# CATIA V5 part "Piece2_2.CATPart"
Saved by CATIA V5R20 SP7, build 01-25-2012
Part number: Pièce2
Bounding box of the stored display mesh (mm): x 0 to 5, y -23.352 to 40.116, z -50.015 to 35.141
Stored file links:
  F:\Piece2_2.CATPart
  C:\Users\ASUS\Desktop\Think Motion IAO\Skl_general.CATPart
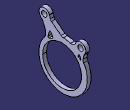
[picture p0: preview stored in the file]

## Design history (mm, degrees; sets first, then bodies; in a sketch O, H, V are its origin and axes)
Body1 (main body)
  Plane1: stored without definition
  Point1 "Point.O": stored without definition
  Point2 "Point.D": stored without definition
  Point3 "Point.D": stored without definition
  Point4 "Point.B": stored without definition
  Point5 "Point.B": stored without definition
  Point6 "Point.D": stored without definition
  Point7 "Point.O": stored without definition
  Sketch1 on Plane1, origin (0, 0, 0), H (0, 1, 0), V (0, 0, 1)
    point P1 (2.9564, 12.9973)
    point P2 (-9.6276, 30.0906)
    point P3 (-22.686, 25.1744)
    arc A1 centre (-16.3583, 28.1678) radius 7 from (-9.6276, 30.0906) to (-21.7119, 23.6578) ccw
    line L1 (22.0467, 10.3647) -> (25.3667, 16.3534)
    point P5 (22.0467, 10.3647)
    line L2 (34.2527, 0.0973) -> (36.2782, 8.4386)
    point P7 (34.2527, 0.0973)
    arc A2 centre (31.305, 13.0613) radius 6.7898 from (36.2782, 8.4386) to (25.3667, 16.3534) ccw
    point P10 (25.3667, 16.3534)
    reference projected point E1 (31.305, 13.0613) from Point5
    reference projected point E2 (-16.3583, 28.1678) from Point6
    arc A3 centre (8.3692, -18.2843) radius 31.7465 from (34.2527, 0.0973) to (-14.5587, 3.6736) cw
    point P12 (34.2527, 0.0973)
    arc A4 centre (8.3692, -18.2843) radius 31.7465 from (22.0467, 10.3647) to (7.0921, 13.4365) ccw
    circle A5 centre (7.024, -18.726) radius 25.5
    reference projected point E3 (7.024, -18.726) from Point7
    arc A6 centre (15.8049, 35.6351) radius 26.0299 from (-9.6276, 30.0906) to (-7.9884, 25.0788) ccw
    axis line L3 (-16.3583, 28.1678) -> (8.3692, -18.2843)
    point P16 (-14.5587, 3.6736)
    point P17 (-21.7119, 23.6578)
    arc A7 centre (-40.513, 5.6558) radius 26.0299 from (-21.7119, 23.6578) to (-14.5587, 3.6736) cw
    line L4 (-7.9884, 25.0788) -> (7.0921, 13.4365)
    point P20 (7.0921, 13.4365)
    point P21 (29.9184, 6.4146)
    line L5 (29.9184, 6.4146) -> (27.7656, 2.2888)
    line L6 (27.7656, 2.2888) -> (31.9929, -0.9748)
    line L7 (31.9929, -0.9748) -> (29.9184, 6.4146)
    point P24 (29.9184, 6.4146)
    point P25 (-8.5711, 13.539)
    line L8 (-8.5711, 13.539) -> (-4.577, 6.0359)
    line L9 (-4.577, 6.0359) -> (-11.9787, 3.0784)
    line L10 (-11.9787, 3.0784) -> (-8.9445, 14.2404)
    point P28 (-8.9445, 14.2404)
    line L11 (-8.9445, 14.2404) -> (-8.5711, 13.539)
    radius A5 = 25.5
    length L8 = 8.5
    coincidence: A1 P3, A2 P10, P10 L1, P12 L2, A3 P1, P7 P12, A6 P5, P20 A3, P21 A2, P24 L5, P24 A2, P25 L3, P28 L3
    tangency: L1 A2, L4 A5, L5 A6, L9 A2
    concentricity: A2 E1, A1 E2, A4 A3, A5 E3
    symmetry: P1 P16 L3, P2 P17 L3, A6 A7 L3
    parallelism: L6 L4, L8 L3
  Pad1: profile Sketch1, direction (1, 0, 0), length 5
  Point8 "Point.B": stored without definition
  DatumPoint1
  Point9 "Point.D": stored without definition
  DatumPoint2
  Sketch2 on end face of Pad1, origin (5, -16.3583, 28.1678), H (0, 1, 0), V (0, 0, 1)
    point P1 (0, 0)
    reference projected point E1 (0, 0) from vertex of DatumPoint1
    coincidence: E1 P1
  Hole1: placed by Sketch2, at (5, -16.3583, 28.1678) direction (-1, 0, 0), diameter 7, depth 10
  Sketch3 on end face of Pad1, origin (5, 31.305, 13.0613), H (0, 1, 0), V (0, 0, 1)
    point P1 (0, 0)
    reference projected point E1 (0, 0) from vertex of DatumPoint2
    coincidence: E1 P1
  Hole2: placed by Sketch3, at (5, 31.305, 13.0613) direction (-1, 0, 0), diameter 7, depth 10
  Fillet1: radius 5, on edge [face of Pad1 from Sketch1.L4 | face of Pad1 from Sketch1.A4]
  Fillet2: radius 5, on edge [face of Pad1 from Sketch1.A6 | face of Pad1 from Sketch1.L4]
  Fillet3: radius 5, on edge [face of Pad1 from Sketch1.A3 | face of Pad1 from Sketch1.A7]
  Fillet4: radius 5, on edge [face of Pad1 from Sketch1.A4 | face of Pad1 from Sketch1.L1]
  Fillet5: radius 5, on edge [face of Pad1 from Sketch1.L2 | face of Pad1 from Sketch1.A3]
  Fillet6: radius 5, on edge [face of Pad1 from Sketch1.A1 | face of Pad1 from Sketch1.A6]
  Fillet7: radius 5, on edge [face of Pad1 from Sketch1.A7 | face of Pad1 from Sketch1.A1]
  Fillet8: radius 1, on edge [face of Pad1 from Sketch1.L10 | face of Pad1 from Sketch1.L9]
  Fillet9: radius 1, on edge [face of Pad1 from Sketch1.L9 | face of Pad1 from Sketch1.L8]
  Fillet10: radius 1, on edge [face of Pad1 from Sketch1.L7 | face of Pad1 from Sketch1.L5]
  Fillet11: radius 1, on edge [face of Pad1 from Sketch1.L5 | face of Pad1 from Sketch1.L6]
  Fillet12: radius 0.3, on edge [face of Pad1 from Sketch1.L6 | face of Pad1 from Sketch1.L7]
  Fillet13: radius 1, on edge [face of Pad1 from Sketch1.L11 | face of Pad1 from Sketch1.L10]
  Fillet14: radius 6, on edge [face of Pad1 from Sketch1.A2 | face of Pad1 from Sketch1.L2]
